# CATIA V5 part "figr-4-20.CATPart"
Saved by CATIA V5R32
Part number: Part1
Bounding box of the stored display mesh (mm): x 0 to 81, y 0 to 160, z -80 to 0
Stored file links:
  D:\PROJECTS\Project 2022\CATIA V5 6R 2022\Resources\Part Files\c04_catia_v5_6r2022_prt\figr-4-20.CATPart
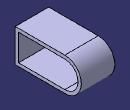
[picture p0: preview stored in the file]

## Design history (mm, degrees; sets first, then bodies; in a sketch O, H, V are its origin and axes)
Body1 (main body)
  Sketch1 on yz-plane, origin (0, 0, 0), H (0, 1, 0), V (0, 0, 1)
    line L1 (0, 0) -> (0, -80)
    line L2 (0, -80) -> (120, -80)
    arc A1 centre (120, -40) radius 40 from (120, -80) to (120, 0) ccw
    line L3 (120, 0) -> (0, 0)
    tangency: A1 L2
  Pad1: profile Sketch1, direction (1, 0, 0), length 81, thin wall 8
